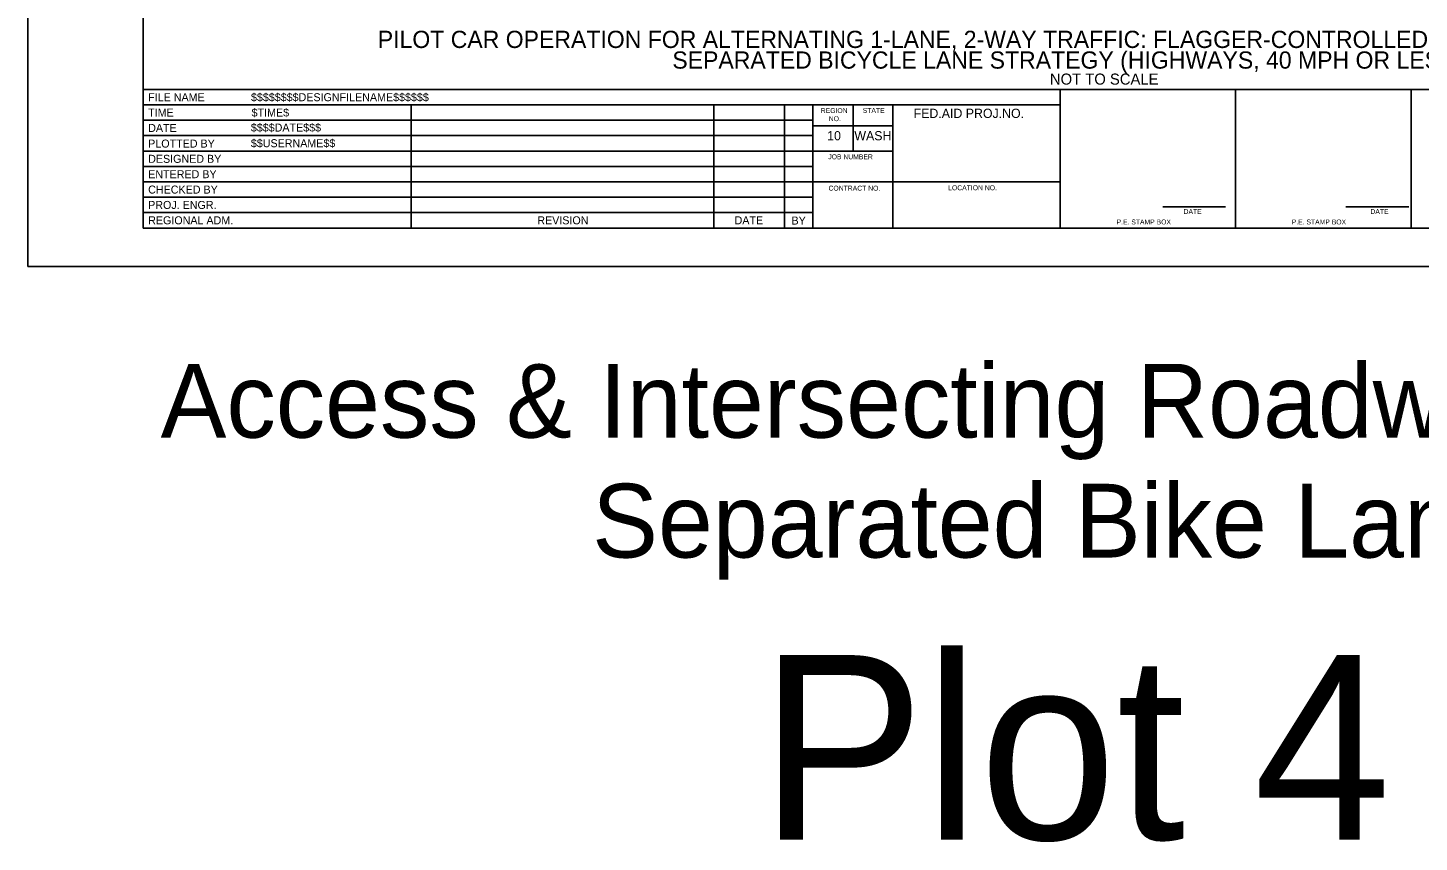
# Model space of a CAD drawing. Extents: x 99998.9 to 100095.7, y 99995 to 100010.7.
# Drawn here: x 100059.06 to 100070.38, y 99995.01 to 100001.63 of the extents above; entities that cross this region are included whole.
import ezdxf

# ---------------------------------------------------------------- set-up
doc = ezdxf.new("R2010")
doc.units = 0
for name, color, linetype in [('SH_DE_DetailHeading1Text', 7, 'Continuous'), ('SH_GI_PlotLimits', 7, 'Continuous'), ('SH_GI_SheetBorder', 7, 'Continuous'), ('SH_GI_SheetLocationText', 7, 'Continuous'), ('SH_GI_SheetTextInCells', 7, 'Continuous'), ('SH_GI_TitleBlockText', 7, 'Continuous')]:
    doc.layers.add(name, color=color, linetype=linetype)

msp = doc.modelspace()

# ---------------------------------------------------------------- linework, layer by layer
at = {"layer": 'SH_GI_PlotLimits'}
msp.add_lwpolyline([(100059.062, 99999.687), (100076.062, 99999.687), (100076.062, 100010.687), (100059.062, 100010.687)], close=True, dxfattribs=at)
at = {"layer": 'SH_GI_SheetBorder'}
for p, q in [((100060, 100010.375), (100060, 100000)), ((100060, 100001.126), (100075.75, 100001.126)), ((100067.457, 100000), (100067.457, 100001.126)), ((100068.883, 100000), (100068.883, 100001.126)), ((100070.309, 100001.126), (100070.309, 100000)), ((100060, 100001.001), (100067.457, 100001.001)), ((100062.179, 100001.001), (100062.179, 100000)), ((100064.641, 100001.001), (100064.641, 100000)), ((100065.216, 100001.001), (100065.216, 100000)), ((100065.445, 100001.001), (100065.445, 100000)), ((100065.772, 100000.625), (100065.772, 100001.001)), ((100066.096, 100000), (100066.096, 100001.001)), ((100060, 100000.876), (100062.182, 100000.876)), ((100062.182, 100000.876), (100065.447, 100000.876)), ((100066.096, 100000.831), (100065.447, 100000.831)), ((100060, 100000.751), (100062.182, 100000.751)), ((100062.182, 100000.751), (100065.447, 100000.751)), ((100060, 100000.625), (100065.447, 100000.625)), ((100066.096, 100000.625), (100065.447, 100000.625)), ((100060, 100000.5), (100065.447, 100000.5)), ((100060, 100000.375), (100065.447, 100000.375)), ((100067.457, 100000.375), (100065.447, 100000.375)), ((100060, 100000.25), (100065.447, 100000.25)), ((100060, 100000.125), (100065.447, 100000.125)), ((100068.29, 100000.173), (100068.802, 100000.173)), ((100069.78, 100000.173), (100070.291, 100000.173)), ((100060, 100000), (100075.75, 100000))]:
    msp.add_line(p, q, dxfattribs=at)

# ---------------------------------------------------------------- texts
at = {"layer": 'SH_DE_DetailHeading1Text'}
for s, height, p in [('PILOT CAR OPERATION FOR ALTERNATING 1-LANE, 2-WAY TRAFFIC: FLAGGER-CONTROLLED + TEMP. RUMBLE STRIPS', 0.14, (100061.908, 100001.464)), ('SEPARATED BICYCLE LANE STRATEGY (HIGHWAYS, 40 MPH OR LESS)', 0.14, (100064.303, 100001.296)), ('NOT TO SCALE', 0.09, (100067.373, 100001.166))]:
    msp.add_text(s, height=height, rotation=360, dxfattribs=at).set_placement(p)
at = {"layer": 'SH_GI_SheetLocationText'}
for s, height, p in [('Access & Intersecting Roadway Details', 0.6, (100060.142, 99998.295)), ('Separated Bike Lane', 0.6, (100063.651, 99997.32)), ('Plot 4', 1.5, (100065.015, 99995.027))]:
    msp.add_text(s, height=height, dxfattribs=at).set_placement(p)
at = {"layer": 'SH_GI_SheetTextInCells'}
for s, height, p in [('FILE NAME', 0.0651, (100060.041, 100001.031)), ('TIME', 0.0651, (100060.041, 100000.906)), ('REGION', 0.04, (100065.51, 100000.935)), ('NO.', 0.04, (100065.575, 100000.869)), ('STATE', 0.04, (100065.851, 100000.936)), ('FED.AID PROJ.NO.', 0.07506, (100066.265, 100000.895)), ('DATE', 0.0651, (100060.041, 100000.781)), ('10', 0.0751, (100065.562, 100000.713)), ('WASH', 0.0751, (100065.783, 100000.713)), ('PLOTTED BY', 0.0651, (100060.041, 100000.654)), ('DESIGNED BY', 0.06505, (100060.041, 100000.53)), ('JOB NUMBER', 0.04, (100065.571, 100000.559)), ('ENTERED BY', 0.0651, (100060.041, 100000.405)), ('CHECKED BY', 0.0651, (100060.041, 100000.28)), ('CONTRACT NO.', 0.04003, (100065.573, 100000.304)), ('LOCATION NO.', 0.04003, (100066.546, 100000.307)), ('PROJ. ENGR.', 0.06505, (100060.041, 100000.155)), ('REGIONAL ADM.', 0.06505, (100060.041, 100000.03)), ('REVISION', 0.0651, (100063.205, 100000.03)), ('DATE', 0.04, (100068.46, 100000.114)), ('DATE', 0.04, (100069.979, 100000.114)), ('DATE', 0.0651, (100064.809, 100000.03)), ('BY', 0.0651, (100065.272, 100000.028)), ('P.E. STAMP BOX', 0.04003, (100067.915, 100000.029)), ('P.E. STAMP BOX', 0.04003, (100069.339, 100000.029))]:
    msp.add_text(s, height=height, dxfattribs=at).set_placement(p)
at = {"layer": 'SH_GI_TitleBlockText'}
for s, height, p in [('$$$$$$$$DESIGNFILENAME$$$$$$', 0.06505, (100060.877, 100001.031)), ('$TIME$', 0.0651, (100060.882, 100000.906)), ('$$$$DATE$$$', 0.06505, (100060.876, 100000.784)), ('$$USERNAME$$', 0.06505, (100060.876, 100000.657))]:
    msp.add_text(s, height=height, dxfattribs=at).set_placement(p)

doc.saveas('drawing.dxf')
